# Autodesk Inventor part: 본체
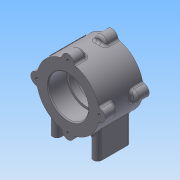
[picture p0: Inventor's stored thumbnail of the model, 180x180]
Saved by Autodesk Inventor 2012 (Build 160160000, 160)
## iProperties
Created: 2015-03
Part Number: 본체
Material: 알루미늄-6061
Document SubType Name: Modeling
Designer: net
Density: 2.71 g/cm^3
Mass: 450.782 g
Surface Area: 332.7 cm^2
Volume: 166.34 cm^3
Author: net
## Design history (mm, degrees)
sketch "스케치1"
  geometry: C1 r 37 at (0, 0); 1 further point
  constraints: 1 centre point, 1 coincident
  dimensions: "d0" = 37 radius of C1
extrude "돌출1" new body sketch "스케치1" distance "d1" = 52; taper "d2" = 0 deg
hole "구멍1" diameter "d5" = 47; stored, may be unused: countersink angle "d9" = 90 deg, drill point angle "d11" = 0 deg; dims "d3" = 10, "d4" = 10, "d6" = 6, "d7" = 4, "d8" = 2, "d10" = 22
hole "구멍2" diameter "d14" = 47; stored, may be unused: countersink angle "d18" = 90 deg, drill point angle "d20" = 0 deg; dims "d12" = 10, "d13" = 10, "d15" = 6, "d16" = 4, "d17" = 2, "d19" = 22
hole "구멍3" diameter "d23" = 42; stored, may be unused: countersink angle "d27" = 90 deg, drill point angle "d29" = 0 deg; dims "d21" = 10, "d22" = 10, "d24" = 6, "d25" = 4, "d26" = 2, "d28" = 22
chamfer "모따기1" distance "d30" = 1; stored, may be unused: second distance "d31" = 2, angle "d32" = 45 deg
fillet "모깎기1" dims "d33" = 0.3
sketch "스케치2"
  geometry: C1 r 7 at (0, 37); 1 further point
  constraints: 2 vertical alignment, 1 centre point, 1 other
  dimensions: "d34" = 7 radius of C1
extrude "돌출2" join sketch "스케치2" distance "d35" = 15; taper "d36" = 0 deg
hole "구멍4" diameter "d39" = 3.242; stored, may be unused: countersink angle "d43" = 90 deg, drill point angle "d45" = 118 deg; dims "d37" = 10, "d38" = 10, "d40" = 8, "d41" = 4, "d42" = 2, "d44" = 11
node "작업 평면1"
fillet "모깎기2" dims "d49" = 3
fillet "모깎기3" dims "d50" = 3
fillet "모깎기4" dims "d51" = 3
fillet "모깎기5" dims "d52" = 3
node "작업 평면2"
sketch "스케치3"
  geometry: L1 (19, -56)-(29, -56); L2 (29, -56)-(29, -21); L3 (29, -21)-(19, -21); L4 (19, -21)-(19, -56); 2 further points
  constraints: 8 end point, 1 horizontal, 1 midpoint, 1 parallel, 1 perpendicular
  dimensions: "d54" = 10 distance of L1.start L1.end; "d55" = 35 distance of L1.end L2.end; "d56" = 10 distance of L2.end L3.end; "d57" = 24 horizontal distance of point (24, -56) point (0, 0); "d58" = 56 vertical distance of L1.end point (0, 0)
extrude "돌출3" join sketch "스케치3" distance "d59" = 40; taper "d60" = 0 deg
fillet "모깎기6" dims "d61" = 5
fillet "모깎기7" dims "d62" = 3
hole "구멍5" diameter "d65" = 4.134; stored, may be unused: countersink angle "d69" = 90 deg, drill point angle "d71" = 118 deg; dims "d63" = 10, "d64" = 10, "d66" = 6, "d67" = 4, "d68" = 2, "d70" = 8
hole "구멍6" diameter "d74" = 4.134; stored, may be unused: countersink angle "d78" = 90 deg, drill point angle "d80" = 118 deg; dims "d72" = 10, "d73" = 10, "d75" = 6, "d76" = 4, "d77" = 2, "d79" = 8
hole "구멍7" diameter "d83" = 4.134; stored, may be unused: countersink angle "d87" = 90 deg, drill point angle "d89" = 118 deg; dims "d81" = 10, "d82" = 10, "d84" = 6, "d85" = 4, "d86" = 2, "d88" = 8
hole "구멍8" diameter "d92" = 4.134; stored, may be unused: countersink angle "d96" = 90 deg, drill point angle "d98" = 118 deg; dims "d90" = 10, "d91" = 10, "d93" = 6, "d94" = 4, "d95" = 2, "d97" = 8
node "작업 평면3"
sketch "스케치4"
  geometry: L1 (0, 0)-(-52.292, 0); L2 (0, 0)-(-26.163, 26.163); A1 r 37 centre (0, 0) between (-9.104, 35.863) and (-35.863, 9.104) reference
  constraints: 4 end point, 1 horizontal, 1 point on circle
  dimensions: "d99" = 45 deg angle of L1 L2
node "작업 평면4"
sketch "스케치5"
  geometry: L1 (-26, -18.921)-(-26, 18.921) reference; L2 (26, -18.921)-(26, 18.921) reference; 3 further points
  constraints: 1 horizontal alignment, 1 midpoint, 1 other
  dimensions: "d100" = 26 distance from line of L1 point (0, 0)
feature "엠보싱1" sketch "스케치5" dims "d101" = 0.5, "d102" = 0
node "솔리드1"
pattern_circular "원형 패턴1" dims angle "d47" = 360 deg
mirror "대칭1"
mirror "대칭2"
other parameters: "d53" = 6
